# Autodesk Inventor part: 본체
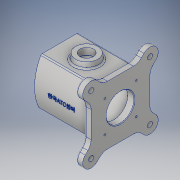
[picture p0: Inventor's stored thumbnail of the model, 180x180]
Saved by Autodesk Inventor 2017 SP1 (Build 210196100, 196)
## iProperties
Part Number: 본체
Material: 알루미늄 6061
Document SubType Name: Modeling
Designer: Administrator
Density: 2.7 g/cm^3
Appearance: 알루미늄 - 평지
Mass: 1224.57 g
Surface Area: 906.054 cm^2
Volume: 453.543 cm^3
Author: Administrator
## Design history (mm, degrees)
sketch "스케치1"
  geometry: L1 (-53, 53)-(53, 53); L2 (53, 53)-(53, -53); L3 (53, -53)-(-53, -53); L4 (-53, -53)-(-53, 53); L5 (-53, 53)-(53, -53); L6 (53, 53)-(-53, -53); L7 (-53.033, 53.033)-(53.033, -53.033); L8 (-63.64, 42.426)-(42.426, -63.64); L9 (63.64, -42.426)-(-42.426, 63.64); L10 (-53.033, -53.033)-(53.033, 53.033); L11 (-42.426, -63.64)-(63.64, 42.426); L12 (42.426, 63.64)-(-63.64, -42.426); C1 r 75 at (0, 0); C2 r 15 at (53, 53); C3 r 15 at (53, -53); C4 r 15 at (-53, 53); C5 r 15 at (-53, -53); A1 r 15 centre (-53.033, 53.033) between (-42.426, 63.64) and (-63.64, 42.426); A2 r 15 centre (53.033, -53.033) between (42.426, -63.64) and (63.64, -42.426); A3 r 15 centre (-53.033, -53.033) between (-63.64, -42.426) and (-42.426, -63.64); A4 r 15 centre (53.033, 53.033) between (63.64, 42.426) and (42.426, 63.64); 1 further point
  constraints: 28 end point, 9 centre point, 8 point on circle, 8 tangent, 5 coincident, 4 midpoint, 4 parallel, 2 collinear, 1 horizontal, 1 perpendicular
  dimensions: "d0" = 150 diameter of C1; "d1" = 106 distance of L2.end L3.end; "d2" = 106 distance of L1.end L2.end; "d3" = 30 diameter of C2; "d4" = 30 diameter of C3; "d5" = 30 diameter of C4; "d6" = 30 diameter of C5; "d126" = 15 radius of A2; "d127" = 150 distance of L7.start L7.end; "d128" = 15 radius of A4; "d129" = 150 distance of L10.start L10.end
extrude "돌출1" new body sketch "스케치1" distance "d7" = 12; taper "d8" = 0 deg
sketch "스케치2"
  geometry: L1 (-45, -45)-(45, -45); L2 (45, -45)-(45, 45); L3 (45, 45)-(-45, 45); L4 (-45, 45)-(-45, -45); L5 (-45, -45)-(45, 45); L6 (45, -45)-(-45, 45); L7 (-45, 0)-(45, 0); L8 (0, 45)-(0, -45); L9 (-32.942, 45)-(32.942, 45); A1 r 90 centre (45, 0) between (-32.942, 45) and (-37.029, -37.029); A2 r 90 centre (-45, 0) between (37.029, -37.029) and (32.942, 45); A3 r 90 centre (0, 45) between (-37.029, -37.029) and (37.029, -37.029); 2 further points
  constraints: 18 end point, 9 point on circle, 5 midpoint, 3 centre point, 3 tangent, 2 parallel, 2 point on line, 1 coincident, 1 collinear, 1 horizontal, 1 perpendicular
  dimensions: "d10" = 90 distance of L2.end L1.end; "d11" = 90 distance of L2.end L3.end; "d107" = 90 radius of A2; "d108" = 90 radius of A1; "d109" = 90 radius of A3
extrude "돌출2" join sketch "스케치2" distance "d12" = 98; taper "d13" = 0 deg
sketch "스케치3"
  geometry: L1 (-45, 45)-(45, 45) reference; L2 (0, 0)-(-28.284, -28.284); L3 (0, -40)-(0, 40); L4 (40, 0)-(-40, 0); L5 (0, 40)-(0, -40); L6 (-40, 0)-(40, 0); A1 r 40 centre (0, 0) between (-28.284, -28.284) and (0, -40); 8 further points
  constraints: 10 end point, 3 coincident, 3 point on circle, 1 centre point, 1 midpoint, 1 vertical, 19 other
  dimensions: "d14" = 80 diameter of A1; "d16" = 45 deg angle of L2 L3; "d19" = 360 deg dimension on L2.start L3.start (derived)
hole "구멍1" sketch "스케치3" at (-28.284, -28.284), (28.284, -28.284), (28.284, 28.284), (-28.284, 28.284) diameter "d21" = 3.242; stored, may be unused: countersink angle "d25" = 90 deg, drill point angle "d27" = 118 deg; dims "d22" = 9, "d23" = 4, "d24" = 2, "d26" = 11
sketch "스케치5"
  geometry: L1 (-45, -45)-(45, -45) reference; L2 (45, 45)-(-45, 45) reference; L3 (-45, -45)-(-45, 45) reference; L4 (45, -45)-(45, 45) reference; L5 (-45, 45)-(45, 45) reference; L6 (-45, -45)-(-45, 45); L7 (45, -45)-(-45, -45) reference; L8 (-45, -45)-(45, -45); L9 (45, 45)-(45, -45) reference; L10 (45, -45)-(45, 45); L11 (-45, 45)-(-45, -45) reference; A1 r 180 centre (0.645, 135) between (-39.941, -40.365) and (45, -39.45); A2 r 180 centre (135, 2.012) between (-39.791, 45) and (-39.941, -40.365); A3 r 180 centre (-135, -2.173) between (39.831, -45) and (38.709, 45); 1 further point
  constraints: 6 end point, 6 point on circle, 4 point on line, 3 centre point, 3 tangent, 2 collinear, 1 vertical
  dimensions: "d104" = 180 radius of A1; "d105" = 180 radius of A3; "d106" = 180 radius of A2
extrude "돌출3" join sketch "스케치5" stored distance "d35" = 110; taper "d36" = 0 deg
sketch "스케치6"
  geometry: L1 (-110, 0)-(0, 0); L2 (-110, 0)-(-110, 25); L3 (-110, 25)-(-98, 25); L4 (-98, 25)-(-98, 37); L5 (-98, 37)-(-12, 37); L6 (-12, 37)-(-12, 25); L7 (-12, 25)-(0, 25); L8 (0, 25)-(0, 0); L9 (0, 31.787)-(0, -31.787) reference; 3 further points
  constraints: 16 end point, 3 perpendicular, 2 horizontal, 1 collinear, 1 midpoint, 1 vertical
  dimensions: "d37" = 50 diameter of L3 L1; "d38" = 74 diameter of L5 L1; "d39" = 50 diameter of L7 L1; "d41" = 12 distance between parallel lines of L9 L6; "d42" = 86 distance of L4.end L5.end (derived)
revolve "회전1" sketch "스케치6" stored, may be unused: angle "d43" = 90 deg
node "작업 평면1"
sketch "스케치8"
  geometry: L1 (0, 31.787)-(0, -31.787) reference; C1 r 20 at (61, 0); C2 r 12 at (61, 0); 3 further points
  constraints: 2 centre point, 1 coincident, 1 horizontal alignment
  dimensions: "d48" = 40 diameter of C1; "d49" = 24 diameter of C2; "d50" = 61 distance from line of C1.centre L1
extrude "돌출4" join sketch "스케치8" stored distance "d51" = 110; taper "d52" = 10 deg
node "작업 평면2"
sketch "스케치14"
  geometry: C1 r 12 at (0, 0); 1 further point
  constraints: 1 centre point
  dimensions: "d97" = 24 diameter of C1
extrude "돌출7" cut sketch "스케치14" distance "d98" = 13; taper "d99" = 0 deg
sketch "스케치10"
  geometry: C1 r 15 at (0, 0); 2 further points
  constraints: 1 centre point, 1 coincident
  dimensions: "d55" = 30 diameter of C1
extrude "돌출6" cut sketch "스케치10" distance "d56" = 20; taper "d57" = 0 deg
sketch "스케치13"
  geometry: L1 (-53, 53)-(0, 0); L2 (-53, -53)-(0, 0); L3 (53, -53)-(0, 0); L4 (53, 53)-(0, 0); C1 r 40 at (0, 0); C2 r 1.621 at (-28.284, 28.284) reference; 5 further points
  constraints: 8 end point, 4 coincident, 1 centre point, 15 other
  dimensions: "d77" = 80 diameter of C1; "d80" = 360 deg dimension on L1.end L1.start (derived)
hole "구멍4" sketch "스케치13" at (-28.284, 28.284), (-28.284, -28.284), (28.284, -28.284), (28.284, 28.284) diameter "d82" = 3.242; stored, may be unused: countersink angle "d86" = 90 deg, drill point angle "d88" = 118 deg; dims "d83" = 9, "d84" = 18, "d85" = 2, "d87" = 11
chamfer "모따기1" distance "d93" = 1; stored, may be unused: second distance "d94" = 2, angle "d95" = 45 deg
chamfer "모따기2" distance "d100" = 1; stored, may be unused: second distance "d101" = 2, angle "d102" = 45 deg
fillet "모깎기5" dims "d103" = 3
fillet "모깎기6" dims "d110" = 3
fillet "모깎기7" dims "d111" = 3
node "작업 평면3"
sketch "스케치15"
  geometry: L1 (-81, 55)-(-41, 55) reference; L2 (0, -31.787)-(0, 31.787) reference; 2 further points
  constraints: 1 other
  dimensions: "d113" = 55 distance from line of point (-61, 0) L1; "d130" = 61 distance from line of L2 point (-61, 0)
feature "엠보싱1" sketch "스케치15" dims "d0" = 150, "d1" = 106, "d2" = 106, "d3" = 30, "d4" = 30, "d5" = 30, "d6" = 30, "d115" = 1, "d116" = 0, "d126" = 15, "d127" = 150, "d128" = 15, "d129" = 150
sketch "스케치16"
  geometry: L1 (0, 0)-(-53.033, 53.033); L2 (0, 0)-(0, 75); L3 (0, 0)-(-75, 0); L4 (0, 0)-(0, -75); L5 (0, 0)-(75, 0); C1 r 26 at (0, 0) reference; A1 r 75 centre (0, 0) between (-53.033, 53.033) and (0, 75); 5 further points
  constraints: 10 end point, 2 coincident, 2 point on circle, 1 centre point, 1 vertical, 17 other
  dimensions: "d131" = 150 diameter of A1; "d132" = 45 deg angle of L1 L2; "d135" = 360 deg dimension on A1.centre L2.end (derived)
hole "구멍5" sketch "스케치16" at (-53.033, 53.033), (-53.033, -53.033), (53.033, -53.033), (53.033, 53.033) diameter "d137" = 9; stored, may be unused: countersink angle "d141" = 90 deg, drill point angle "d143" = 118 deg; dims "d138" = 9, "d139" = 18, "d140" = 2, "d142" = 15
fillet "모깎기8" dims "d144" = 20
fillet "모깎기9" dims "d145" = 3
node "솔리드1"
other parameters: "d47" = 55, "d112" = 55
